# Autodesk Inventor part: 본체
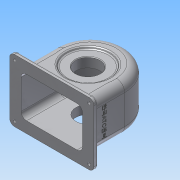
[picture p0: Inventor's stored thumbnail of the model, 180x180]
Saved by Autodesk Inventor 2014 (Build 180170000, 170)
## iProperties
Created: 2016-01
Part Number: 본체
Material: 알루미늄 6061
Document SubType Name: Modeling
Designer: net
Density: 2.71 g/cm^3
Appearance: 알루미늄 - 평지
Mass: 809.574 g
Surface Area: 999.745 cm^2
Volume: 298.736 cm^3
Author: net
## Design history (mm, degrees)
sketch "스케치1"
  geometry: L1 (-57, -64)-(57, -64); L2 (57, -64)-(57, 57); L3 (57, 57)-(-57, 57); L4 (-57, 57)-(-57, -64); 2 further points
  constraints: 8 end point, 2 parallel, 1 horizontal, 1 midpoint, 1 perpendicular, 1 vertical alignment
  dimensions: "d0" = 114 distance of L1.start L1.end; "d1" = 121 distance of L1.end L2.end; "d2" = 64 distance from line of L1 point (0, 0)
extrude "돌출1" new body sketch "스케치1" stored distance "d3" = 77; taper "d4" = 0 deg
fillet "모깎기1" dims "d5" = 57
fillet "모깎기2" dims "d6" = 14
sketch "스케치2"
  geometry: L1 (86, 0)-(0, 0) reference; L2 (100, 14)-(100, 63) reference; L3 (0, 77)-(86, 77) reference; L4 (-14, 63)-(-14, 14) reference; L5 (-19, 90.5)-(105, 90.5); L6 (113, 82.5)-(113, -5.5); L7 (105, -13.5)-(-19, -13.5); L8 (-27, -5.5)-(-27, 82.5); C1 r 2.5 at (-19, 82.5); C2 r 2.5 at (-19, -5.5); C3 r 2.5 at (105, -5.5); C4 r 2.5 at (105, 82.5); A1 r 14 centre (0, 14) between (-14, 14) and (0, 0) reference; A2 r 14 centre (86, 14) between (86, 0) and (100, 14) reference; A3 r 14 centre (86, 63) between (100, 63) and (86, 77) reference; A4 r 14 centre (0, 63) between (0, 77) and (-14, 63) reference; A5 r 8 centre (-19, 82.5) between (-19, 90.5) and (-27, 82.5); A6 r 8 centre (-19, -5.5) between (-27, -5.5) and (-19, -13.5); A7 r 8 centre (105, -5.5) between (105, -13.5) and (113, -5.5); A8 r 8 centre (105, 82.5) between (113, 82.5) and (105, 90.5); 8 further points
  constraints: 8 centre point, 8 end point, 8 point on circle, 8 tangent, 6 point on line, 4 coincident, 4 midpoint, 3 equal radius, 2 parallel, 1 horizontal, 1 horizontal alignment, 1 perpendicular, 1 vertical alignment
  dimensions: "d7" = 140 distance of point (-27, 90.5) point (113, 90.5); "d8" = 104 distance of point (113, 90.5) point (113, -13.5); "d9" = 8 radius of A5; "d10" = 8 radius of A6; "d11" = 8 radius of A7; "d12" = 8 radius of A8; "d13" = 5 diameter of C1
extrude "돌출2" join sketch "스케치2" distance "d14" = 7; taper "d15" = 0 deg
sketch "스케치4"
  geometry: L1 (-57, -57)-(-57, 0) reference; L2 (57, 0)-(57, -57) reference; L3 (-51, -64)-(-51, 0); L4 (51, 0)-(51, -64); L5 (-62, -64)-(62, -64) reference; A1 r 57 centre (0, 0) between (57, 0) and (-57, 0) reference; A2 r 51 centre (0, 0) between (51, 0) and (-51, 0); 1 further point
  constraints: 4 end point, 2 point on circle, 2 point on line, 1 centre point
  dimensions: "d21" = 6 radial gap between concentric circles of A2 A1; "d22" = 6 distance between parallel lines of L2 L4; "d23" = 6 distance between parallel lines of L1 L3
extrude "돌출3" cut sketch "스케치4" stored distance "d24" = 67; taper "d25" = 0 deg
fillet "모깎기3" dims "d26" = 9
node "작업 평면1"
sketch "스케치5"
  geometry: C1 r 6 at (-62, 52); 1 further point
  constraints: 1 centre point, 1 coincident
  dimensions: "d28" = 12 diameter of C1
extrude "돌출4" join sketch "스케치5" stored distance "d29" = 67; taper "d30" = 0 deg
fillet "모깎기4" dims "d31" = 3
hole "구멍1" diameter "d34" = 4.459; stored, may be unused: countersink angle "d38" = 90 deg, drill point angle "d40" = 0 deg; dims "d32" = 10, "d33" = 10, "d35" = 6, "d36" = 4, "d37" = 2, "d39" = 8
sketch "스케치11"
  geometry: L1 (42, 33.5)-(0, 33.5) reference; L2 (0, 38.5)-(43, 38.5) reference; L3 (0, 33.5)-(-64, 33.5) reference; L4 (-57, 38.5)-(0, 38.5) reference; L5 (-4, 38.5)-(-4, 19.5); L6 (-4, 19.5)-(24, 19.5); L7 (24, 19.5)-(39.943, 38.5); L8 (39.943, 38.5)-(-4, 38.5); L9 (33.416, 38.5)-(30.899, 35.5); L10 (30.899, 35.5)-(-4, 35.5); L11 (-64, -24.5)-(-64, 24.5) reference; 1 further point
  constraints: 12 end point, 4 point on line, 2 horizontal, 1 parallel, 1 vertical
  dimensions: "d112" = 56 diameter of L6.end L5; "d113" = 3 distance between parallel lines of L10 L2; "d114" = 5 distance between parallel lines of L9 L7; "d115" = 16 distance between parallel lines of L6 L10; "d116" = 50 deg angle of L6 L7; "d117" = 60 distance between parallel lines of L11 L5
revolve "회전3" stored, may be unused: angle "d118" = 90 deg
revolve "회전4" stored, may be unused: angle "d119" = 90 deg
sketch "스케치12"
  geometry: L1 (62, -64)-(-62, -64) reference; C1 r 31 at (0, -4); A1 r 43 centre (0, 0) between (43, 0) and (-43, 0) reference
  constraints: 1 centre point, 1 vertical alignment
  dimensions: "d120" = 62 diameter of C1; "d121" = 60 distance from line of L1 C1.centre
extrude "돌출6" join sketch "스케치12" distance "d122" = 10; taper "d123" = 0 deg
hole "구멍6" diameter "d126" = 40; stored, may be unused: countersink angle "d130" = 90 deg, drill point angle "d132" = 0 deg; dims "d124" = 10, "d125" = 10, "d127" = 6, "d128" = 4, "d129" = 2, "d131" = 15
hole "구멍7" diameter "d135" = 40; stored, may be unused: countersink angle "d139" = 90 deg, drill point angle "d141" = 0 deg; dims "d133" = 10, "d134" = 10, "d136" = 6, "d137" = 4, "d138" = 2, "d140" = 15
fillet "모깎기10" dims "d142" = 3
fillet "모깎기11" dims "d143" = 1
fillet "모깎기12" dims "d144" = 3
chamfer "모따기2" distance "d145" = 1; stored, may be unused: second distance "d146" = 2, angle "d147" = 45 deg
sketch "스케치13"
  geometry: L1 (68.5, -64)-(-19.5, -64) reference; L2 (-14, -13.054)-(-14, -56) reference; 2 further points
  constraints: 1 other
  dimensions: "d148" = 30 distance from line of L1 point (24.5, -34); "d149" = 38.5 distance from line of point (24.5, -34) L2
feature "엠보싱2" sketch "스케치13" dims "d150" = 0.5, "d151" = 0
sketch "스케치6"
  geometry: C1 r 31 at (0, 0); A1 r 43 centre (0, 0) between (43, 0) and (-43, 0) reference
  constraints: 1 centre point, 1 coincident
  dimensions: "d41" = 62 diameter of C1
extrude "돌출5" join sketch "스케치6" distance "d42" = 10; taper "d43" = 0 deg
fillet "모깎기5" dims "d44" = 3
hole "구멍2" diameter "d47" = 40; stored, may be unused: countersink angle "d51" = 90 deg, drill point angle "d53" = 0 deg; dims "d45" = 10, "d46" = 10, "d48" = 6, "d49" = 4, "d50" = 2, "d52" = 15
sketch "스케치7"
  geometry: L1 (42, 33.5)-(0, 33.5) reference; L2 (0, 38.5)-(43, 38.5) reference; L3 (-64, -24.5)-(-64, 24.5) reference; L4 (0, 33.5)-(-64, 33.5) reference; L5 (-57, 38.5)-(0, 38.5) reference; L6 (43, 38.5)-(27.057, 19.5); L7 (36.473, 38.5)-(33.956, 35.5); L8 (27.057, 19.5)-(-4, 19.5); L9 (0, 24.5)-(0, -24.5) reference; L10 (33.956, 35.5)-(-4, 35.5); L11 (43, 38.5)-(36.473, 38.5); L12 (-4, 38.5)-(-4, 19.5); L13 (36.473, 38.5)-(-4, 38.5); 2 further points
  constraints: 14 end point, 6 point on line, 4 horizontal, 1 parallel, 1 vertical
  dimensions: "d60" = 5 distance between parallel lines of L7 L6; "d61" = 3 distance between parallel lines of L10 L2; "d62" = 50 deg angle of L8 L6; "d65" = 16 distance between parallel lines of L8 L10; "d110" = 60 distance between parallel lines of L3 L12; "d111" = 0 distance from line of L2.end L6
revolve "회전1" stored, may be unused: angle "d66" = 90 deg
revolve "회전2" stored, may be unused: angle "d67" = 90 deg
hole "구멍3" diameter "d70" = 40; stored, may be unused: countersink angle "d74" = 90 deg, drill point angle "d76" = 0 deg; dims "d68" = 10, "d69" = 10, "d71" = 6, "d72" = 4, "d73" = 2, "d75" = 15
chamfer "모따기1" distance "d77" = 1; stored, may be unused: second distance "d78" = 2, angle "d79" = 45 deg
fillet "모깎기6" dims "d80" = 3
fillet "모깎기7" dims "d81" = 3
sketch "스케치8"
  geometry: C1 r 21 at (0, 0) reference; 1 further point
  constraints: 1 vertical alignment
  dimensions: "d82" = 28 distance of C1.centre point (0, 28)
hole "구멍4" sketch "스케치8" at (0, 28) diameter "d83" = 2.459; stored, may be unused: countersink angle "d87" = 90 deg, drill point angle "d89" = 118 deg; dims "d84" = 7, "d85" = 4, "d86" = 2, "d88" = 9
sketch "스케치9"
  geometry: C1 r 31 at (0, 0) reference; 1 further point
  constraints: 1 vertical alignment
  dimensions: "d93" = 24 distance of C1.centre point (0, 24)
hole "구멍5" sketch "스케치9" at (0, 24) diameter "d94" = 2.459; stored, may be unused: countersink angle "d98" = 90 deg, drill point angle "d100" = 118 deg; dims "d95" = 6, "d96" = 4, "d97" = 2, "d99" = 8
fillet "모깎기8" dims "d104" = 3
fillet "모깎기9" dims "d105" = 1
sketch "스케치10"
  geometry: L1 (68.5, -64)-(-19.5, -64) reference; L2 (-14, 0)-(-14, -56) reference; 3 further points
  constraints: 1 other
  dimensions: "d106" = 30 distance from line of L1 point (24.5, -34); "d107" = 38.5 distance from line of point (24.5, -34) L2
feature "엠보싱1" sketch "스케치10" dims "d108" = 0.5, "d109" = 0
node "솔리드1"
pattern_circular "원형 패턴1" dims angle "d91" = 360 deg
pattern_circular "원형 패턴2" dims angle "d102" = 360 deg
other parameters: "d27" = -127
